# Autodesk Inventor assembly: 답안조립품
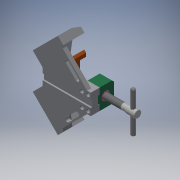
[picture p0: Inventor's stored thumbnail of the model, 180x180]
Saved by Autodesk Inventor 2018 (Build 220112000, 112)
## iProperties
Created: 2020-05
Part Number: 답안조립품
Document SubType Name: Assembly
Designer: 1class 18
Author: 1class 18
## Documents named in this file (11)
- C:\Users\1class 18\Desktop\700506V1049\답안조립품.iam
- C:\Users\1class 18\Desktop\700506V1049\베이스.ipt
- C:\Users\1class 18\Desktop\700506V1049\리드스크류.ipt
- C:\Users\1class 18\Desktop\700506V1049\핸들.ipt
- C:\Users\1class 18\Desktop\700506V1049\멈춤나사 M4x5.ipt
- C:\Users\1class 18\Desktop\700506V1049\부시.ipt
- C:\Users\1class 18\Desktop\700506V1049\서포트.ipt
- C:\Users\1class 18\Desktop\700506V1049\멈춤나사 M4x10.ipt
- C:\Users\1class 18\Desktop\700506V1049\조.ipt
- C:\Users\1class 18\Desktop\700506V1049\평행 핀 2.5x24.ipt
- C:\Users\1class 18\Desktop\700506V1049\볼트 M4x16.ipt
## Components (1 placed, 1 different names)
1. 핸들:1
